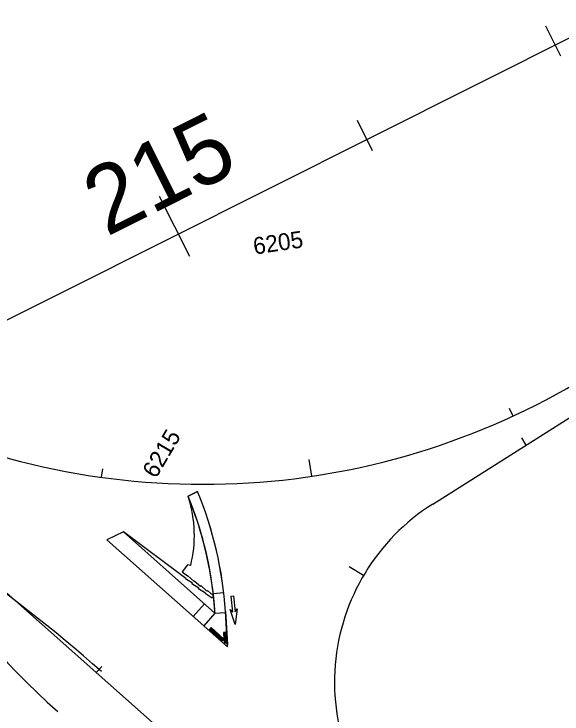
# Model space of a CAD drawing. Extents: x -5665 to 1997148, y 4 to 827579.
# Drawn here: x 1971710.3 to 1971970.2, y 802511.9 to 802844 of the extents above; entities that cross this region are included whole.
import ezdxf

# ---------------------------------------------------------------- set-up
doc = ezdxf.new("R2010")
doc.units = 0
for name, color, linetype in [('RD_HC_CL_Rel', 7, 'Continuous'), ('RD_HC_Data_Tic_Rel', 7, 'Continuous'), ('RD_HC_TX_Rel_Sta50', 7, 'Continuous'), ('RD_PD_SW', 7, 'Continuous'), ('RD_Sketch8', 7, 'Continuous')]:
    doc.layers.add(name, color=color, linetype=linetype)

msp = doc.modelspace()

# ---------------------------------------------------------------- linework, layer by layer
at = {"layer": 'RD_HC_CL_Rel'}
for p, q in [((1971733.64, 802712.2), (1977177.45, 805443.11)), ((1970807.31, 803367.72), (1971858, 802435.06)), ((1971908.89, 802611.51), (1972136.99, 802755.6))]:
    msp.add_line(p, q, dxfattribs=at)
for centre, radius, start, end in [((1971866.23, 802750.94), 250, 104.6451, 193.7973), ((1970020.89, 806126.39), 3819.72, 269.57213, 296.64085), ((1971287.07, 802008.53), 700, 48.40581, 77.87082), ((1971963.34, 802774.78), 350, 193.7973, 228.4058), ((1971799.96, 802970.88), 350, 244.776, 302.2824), ((1971962.3, 802526.96), 100, 122.2824, 228.2399)]:
    msp.add_arc(centre, radius, start, end, dxfattribs=at)
at = {"layer": 'RD_HC_Data_Tic_Rel'}
for p, q in [((1971969.76, 802823.93), (1971962.59, 802838.24)), ((1971880.38, 802779.09), (1971873.2, 802793.4)), ((1971793.68, 802728.89), (1971779.33, 802757.49)), ((1971947, 802653.26), (1971945.32, 802656.89)), ((1971953.25, 802639.53), (1971951.11, 802642.91)), ((1971851.52, 802624.69), (1971850.34, 802632.61)), ((1971751.86, 802624.2), (1971752.41, 802628.16)), ((1971876.12, 802577.69), (1971869.23, 802581.75)), ((1971749.32, 802531.53), (1971751.98, 802534.52))]:
    msp.add_line(p, q, dxfattribs=at)
at = {"layer": 'RD_PD_SW'}
for p, q in [((1971792.87, 802615.22), (1971797.35, 802617.46)), ((1971793.45, 802615.51), (1971792.87, 802615.22)), ((1971797.35, 802617.46), (1971793.45, 802615.51)), ((1971762.24, 802598.28), (1971754.32, 802594.62)), ((1971791.72, 802576.19), (1971762.24, 802598.28)), ((1971762.24, 802598.28), (1971805.61, 802559.79)), ((1971762.24, 802598.28), (1971805.61, 802559.79)), ((1971805.61, 802559.79), (1971762.24, 802598.28)), ((1971754.32, 802594.62), (1971811.63, 802543.74)), ((1971754.32, 802594.62), (1971811.63, 802543.74)), ((1971792.59, 802582.72), (1971790.08, 802579.3)), ((1971794.09, 802582.35), (1971792.63, 802582.71)), ((1971790.08, 802579.3), (1971792.62, 802577.39)), ((1971791.61, 802576.04), (1971791.72, 802576.19)), ((1971794.89, 802573.94), (1971791.61, 802576.04)), ((1971792.62, 802577.39), (1971792.69, 802577.48)), ((1971792.69, 802577.48), (1971795.61, 802574.9)), ((1971795.61, 802574.9), (1971795.79, 802575.14)), ((1971795.79, 802575.14), (1971798.72, 802572.57)), ((1971794.71, 802573.7), (1971794.89, 802573.94)), ((1971798, 802571.61), (1971794.71, 802573.7)), ((1971797.82, 802571.37), (1971798, 802571.61)), ((1971798.72, 802572.57), (1971798.9, 802572.81)), ((1971798.9, 802572.81), (1971801.82, 802570.24)), ((1971801.1, 802569.28), (1971797.82, 802571.37)), ((1971800.92, 802569.04), (1971801.1, 802569.28)), ((1971804.21, 802566.94), (1971800.92, 802569.04)), ((1971801.82, 802570.24), (1971802.01, 802570.48)), ((1971802.01, 802570.48), (1971804.92, 802567.91)), ((1971809.78, 802569.44), (1971804.82, 802568.88)), ((1971804.92, 802567.91), (1971804.93, 802567.9)), ((1971804.93, 802567.9), (1971804.92, 802567.89)), ((1971795.32, 802558.22), (1971800.63, 802564.21)), ((1971805.61, 802559.79), (1971800.3, 802553.8)), ((1971805.61, 802559.79), (1971805.59, 802560.17)), ((1971805.59, 802560.17), (1971805.59, 802560.17)), ((1971805.59, 802560.17), (1971805.61, 802559.79)), ((1971805.61, 802559.79), (1971810.6, 802560.1)), ((1971805.61, 802559.82), (1971805.61, 802559.79)), ((1971811.63, 802543.74), (1971810.58, 802560.49)), ((1971810.58, 802560.49), (1971811.56, 802544.95))]:
    msp.add_line(p, q, dxfattribs=at)
for points in [[(1971792.63, 802582.71), (1971792.59, 802582.72), (1971790.08, 802579.3)], [(1971801.1, 802569.28), (1971801.1, 802569.28)], [(1971804.92, 802567.91), (1971804.57, 802567.43), (1971804.21, 802566.94)], [(1971805.59, 802560.17), (1971805.59, 802560.17)]]:
    msp.add_lwpolyline(points, dxfattribs=at)
for points in [[(1971807.46, 802549.56), (1971803.74, 802552.88), (1971802.67, 802551.69), (1971806.39, 802548.37)], [(1971809.84, 802547.43), (1971806.12, 802550.75), (1971805.06, 802549.56), (1971808.78, 802546.24)], [(1971809.6, 802550.58), (1971809.91, 802545.6), (1971811.51, 802545.7), (1971811.2, 802550.67)]]:
    msp.add_lwpolyline(points, close=True, dxfattribs=at)
for centre, radius in [((1971803.09, 802551.71), 0.146), ((1971803.09, 802551.71), 0.073), ((1971803.43, 802552.08), 0.146), ((1971803.43, 802552.08), 0.073), ((1971803.73, 802551.81), 0.146), ((1971803.77, 802552.46), 0.146), ((1971803.73, 802551.81), 0.073), ((1971803.77, 802552.46), 0.073), ((1971804.02, 802551.55), 0.146), ((1971804.06, 802552.19), 0.146), ((1971804.06, 802552.19), 0.073), ((1971804.36, 802551.93), 0.146), ((1971804.36, 802551.93), 0.073), ((1971804.66, 802551.66), 0.146), ((1971804.66, 802551.66), 0.073), ((1971803.39, 802551.44), 0.146), ((1971803.39, 802551.44), 0.073), ((1971803.69, 802551.17), 0.146), ((1971803.69, 802551.17), 0.073), ((1971803.99, 802550.91), 0.146), ((1971803.99, 802550.91), 0.073), ((1971804.02, 802551.55), 0.073), ((1971804.29, 802550.64), 0.146), ((1971804.32, 802551.28), 0.146), ((1971804.29, 802550.64), 0.073), ((1971804.32, 802551.28), 0.073), ((1971804.59, 802550.37), 0.146), ((1971804.62, 802551.01), 0.146), ((1971804.59, 802550.37), 0.073), ((1971804.62, 802551.01), 0.073), ((1971804.89, 802550.11), 0.146), ((1971804.92, 802550.75), 0.146), ((1971804.96, 802551.39), 0.146), ((1971804.89, 802550.11), 0.073), ((1971804.92, 802550.75), 0.073), ((1971804.96, 802551.39), 0.073), ((1971805.18, 802549.84), 0.146), ((1971805.22, 802550.48), 0.146), ((1971805.26, 802551.13), 0.146), ((1971805.18, 802549.84), 0.073), ((1971805.22, 802550.48), 0.073), ((1971805.26, 802551.13), 0.073), ((1971805.48, 802549.58), 0.146), ((1971805.48, 802549.58), 0.146), ((1971805.52, 802550.21), 0.146), ((1971805.56, 802550.86), 0.146), ((1971805.48, 802549.58), 0.073), ((1971805.48, 802549.58), 0.073), ((1971805.52, 802550.21), 0.073), ((1971805.56, 802550.86), 0.073), ((1971805.78, 802549.31), 0.146), ((1971805.78, 802549.31), 0.146), ((1971805.82, 802549.95), 0.146), ((1971805.82, 802549.95), 0.146), ((1971805.86, 802550.59), 0.146), ((1971805.78, 802549.31), 0.073), ((1971805.78, 802549.31), 0.073), ((1971805.82, 802549.95), 0.073), ((1971805.82, 802549.95), 0.073), ((1971805.86, 802550.59), 0.073), ((1971806.08, 802549.04), 0.146), ((1971806.08, 802549.04), 0.146), ((1971806.11, 802549.68), 0.146), ((1971806.11, 802549.68), 0.146), ((1971806.15, 802550.33), 0.146), ((1971806.15, 802550.33), 0.146), ((1971806.08, 802549.04), 0.073), ((1971806.08, 802549.04), 0.073), ((1971806.11, 802549.68), 0.073), ((1971806.11, 802549.68), 0.073), ((1971806.15, 802550.33), 0.073), ((1971806.15, 802550.33), 0.073), ((1971806.38, 802548.78), 0.146), ((1971806.38, 802548.78), 0.146), ((1971806.41, 802549.42), 0.146), ((1971806.41, 802549.42), 0.146), ((1971806.45, 802550.06), 0.146), ((1971806.45, 802550.06), 0.146), ((1971806.38, 802548.78), 0.073), ((1971806.38, 802548.78), 0.073), ((1971806.41, 802549.42), 0.073), ((1971806.41, 802549.42), 0.073), ((1971806.45, 802550.06), 0.073), ((1971806.45, 802550.06), 0.073), ((1971806.68, 802548.51), 0.146), ((1971806.71, 802549.15), 0.146), ((1971806.71, 802549.15), 0.146), ((1971806.68, 802548.51), 0.073), ((1971806.75, 802549.8), 0.146), ((1971806.75, 802549.8), 0.146), ((1971806.71, 802549.15), 0.073), ((1971806.71, 802549.15), 0.073), ((1971806.75, 802549.8), 0.073), ((1971806.75, 802549.8), 0.073), ((1971806.98, 802548.24), 0.146), ((1971807.01, 802548.88), 0.146), ((1971807.05, 802549.53), 0.146), ((1971807.05, 802549.53), 0.146), ((1971807.01, 802548.88), 0.073), ((1971807.05, 802549.53), 0.073), ((1971807.05, 802549.53), 0.073), ((1971807.31, 802548.62), 0.146), ((1971807.35, 802549.26), 0.146), ((1971807.31, 802548.62), 0.073), ((1971807.35, 802549.26), 0.073), ((1971807.61, 802548.35), 0.146), ((1971807.65, 802549), 0.146), ((1971807.61, 802548.35), 0.073), ((1971807.65, 802549), 0.073), ((1971807.95, 802548.73), 0.146), ((1971807.95, 802548.73), 0.073), ((1971808.24, 802548.46), 0.146), ((1971808.24, 802548.46), 0.073), ((1971809.91, 802550.31), 0.146), ((1971809.94, 802549.91), 0.146), ((1971809.96, 802549.51), 0.146), ((1971809.91, 802550.31), 0.073), ((1971809.99, 802549.11), 0.146), ((1971809.94, 802549.91), 0.073), ((1971810.01, 802548.72), 0.146), ((1971809.96, 802549.51), 0.073), ((1971810.04, 802548.32), 0.146), ((1971809.99, 802549.11), 0.073), ((1971810.01, 802548.72), 0.073), ((1971810.04, 802548.32), 0.073), ((1971810.42, 802550.34), 0.146), ((1971810.45, 802549.95), 0.146), ((1971810.47, 802549.55), 0.146), ((1971810.42, 802550.34), 0.073), ((1971810.5, 802549.15), 0.146), ((1971810.45, 802549.95), 0.073), ((1971810.52, 802548.75), 0.146), ((1971810.47, 802549.55), 0.073), ((1971810.55, 802548.35), 0.146), ((1971810.5, 802549.15), 0.073), ((1971810.52, 802548.75), 0.073), ((1971810.55, 802548.35), 0.073), ((1971810.92, 802550.38), 0.146), ((1971810.95, 802549.98), 0.146), ((1971810.97, 802549.58), 0.146), ((1971810.92, 802550.38), 0.073), ((1971810.99, 802549.18), 0.146), ((1971810.95, 802549.98), 0.073), ((1971811.02, 802548.78), 0.146), ((1971810.97, 802549.58), 0.073), ((1971811.04, 802548.38), 0.146), ((1971810.99, 802549.18), 0.073), ((1971811.02, 802548.78), 0.073), ((1971811.04, 802548.38), 0.073), ((1971806.98, 802548.24), 0.073), ((1971807.27, 802547.98), 0.146), ((1971807.27, 802547.98), 0.073), ((1971807.57, 802547.71), 0.146), ((1971807.57, 802547.71), 0.073), ((1971807.87, 802547.45), 0.146), ((1971807.9, 802548.08), 0.146), ((1971807.87, 802547.45), 0.073), ((1971807.9, 802548.08), 0.073), ((1971808.17, 802547.18), 0.146), ((1971808.2, 802547.82), 0.146), ((1971808.17, 802547.18), 0.073), ((1971808.2, 802547.82), 0.073), ((1971808.47, 802546.91), 0.146), ((1971808.5, 802547.55), 0.146), ((1971808.54, 802548.2), 0.146), ((1971808.47, 802546.91), 0.073), ((1971808.5, 802547.55), 0.073), ((1971808.54, 802548.2), 0.073), ((1971808.77, 802546.65), 0.146), ((1971808.8, 802547.29), 0.146), ((1971808.84, 802547.93), 0.146), ((1971808.77, 802546.65), 0.073), ((1971808.8, 802547.29), 0.073), ((1971808.84, 802547.93), 0.073), ((1971809.1, 802547.02), 0.146), ((1971809.14, 802547.67), 0.146), ((1971809.1, 802547.02), 0.073), ((1971809.14, 802547.67), 0.073), ((1971809.44, 802547.4), 0.146), ((1971809.44, 802547.4), 0.073), ((1971810.06, 802547.92), 0.146), ((1971810.09, 802547.52), 0.146), ((1971810.11, 802547.12), 0.146), ((1971810.06, 802547.92), 0.073), ((1971810.14, 802546.72), 0.146), ((1971810.09, 802547.52), 0.073), ((1971810.16, 802546.32), 0.146), ((1971810.11, 802547.12), 0.073), ((1971810.19, 802545.92), 0.146), ((1971810.14, 802546.72), 0.073), ((1971810.16, 802546.32), 0.073), ((1971810.19, 802545.92), 0.073), ((1971810.57, 802547.95), 0.146), ((1971810.6, 802547.55), 0.146), ((1971810.62, 802547.15), 0.146), ((1971810.57, 802547.95), 0.073), ((1971810.65, 802546.75), 0.146), ((1971810.6, 802547.55), 0.073), ((1971810.67, 802546.35), 0.146), ((1971810.62, 802547.15), 0.073), ((1971810.7, 802545.95), 0.146), ((1971810.65, 802546.75), 0.073), ((1971810.67, 802546.35), 0.073), ((1971810.7, 802545.95), 0.073), ((1971811.07, 802547.98), 0.146), ((1971811.09, 802547.58), 0.146), ((1971811.12, 802547.18), 0.146), ((1971811.07, 802547.98), 0.073), ((1971811.14, 802546.78), 0.146), ((1971811.09, 802547.58), 0.073), ((1971811.17, 802546.38), 0.146), ((1971811.12, 802547.18), 0.073), ((1971811.19, 802545.98), 0.146), ((1971811.14, 802546.78), 0.073), ((1971811.17, 802546.38), 0.073), ((1971811.19, 802545.98), 0.073)]:
    msp.add_circle(centre, radius, dxfattribs=at)
for centre, radius, start, end in [((1971632.93, 802549.27), 173, 3.4857, 22.4095), ((1971633.02, 802549.29), 172.9, 6.1814, 22.4141), ((1971632.93, 802549.27), 178, 3.6139, 22.5273), ((1971633, 802549.28), 177.92, 3.6099, 22.5314), ((1971632.93, 802549.27), 173, 6.186, 22.1874), ((1971735.84, 802596.74), 60, 346.1233, 17.318), ((1971632.93, 802549.27), 173, 3.6139, 6.186), ((1971632.93, 802549.27), 173, 3.4956, 6.1811), ((1971811.06, 802544.92), 0.5, 228.4058, 3.6139)]:
    msp.add_arc(centre, radius, start, end, dxfattribs=at)
at = {"layer": 'RD_Sketch8'}
for p, q in [((1971813.36, 802567.86), (1971814.4, 802567.96)), ((1971814.1, 802560.21), (1971813.36, 802567.86)), ((1971814.4, 802567.96), (1971815.13, 802560.31)), ((1971815.13, 802560.31), (1971816.17, 802561.76)), ((1971816.17, 802561.76), (1971815.18, 802554.43)), ((1971815.18, 802554.43), (1971812.8, 802561.44)), ((1971812.8, 802561.44), (1971814.1, 802560.21))]:
    msp.add_line(p, q, dxfattribs=at)

# ---------------------------------------------------------------- texts
at = {"layer": 'RD_HC_TX_Rel_Sta50'}
for s, height, rotation, p in [('215', 32, 26.6408, (1971754.2, 802738.17)), ('6205', 8, 8.4709, (1971824.34, 802729.84)), ('6215', 8, 59.5186, (1971777.63, 802623.27))]:
    msp.add_text(s, height=height, rotation=rotation, dxfattribs=at).set_placement(p)

doc.saveas('drawing.dxf')
